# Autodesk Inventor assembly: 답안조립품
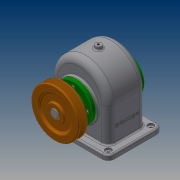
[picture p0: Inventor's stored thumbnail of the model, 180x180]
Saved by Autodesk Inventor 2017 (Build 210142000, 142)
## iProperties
Part Number: 답안조립품
Material: 일반
Document SubType Name: Assembly
Designer: 20
Author: 20
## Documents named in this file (13)
- C:\Users\20\Desktop\480310V1012\답안조립품.iam
- C:\Users\20\Desktop\480310V1012\본체.ipt
- C:\Users\20\Desktop\480310V1012\뒤커버.ipt
- C:\Users\20\Desktop\480310V1012\앞커버.ipt
- C:\Users\20\Desktop\480310V1012\베어링 6203.ipt
- C:\Users\20\Desktop\480310V1012\오일 실 28 40 8.ipt
- C:\Users\20\Desktop\480310V1012\축.ipt
- C:\Users\20\Desktop\480310V1012\스퍼기어.ipt
- C:\Users\20\Desktop\480310V1012\키 6x6x22.ipt
- C:\Users\20\Desktop\480310V1012\V-벨트풀리.ipt
- C:\Users\20\Desktop\480310V1012\키 5x5x18.ipt
- C:\Users\20\Desktop\480310V1012\멈춤나사 M4.ipt
- C:\Users\20\Desktop\480310V1012\볼트 M4.ipt
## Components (1 placed, 1 different names)
1. V-벨트풀리:1 — 플러쉬:2
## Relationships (1: Flush 1)
- 플러쉬:2 [Flush]: V-벨트풀리:1
